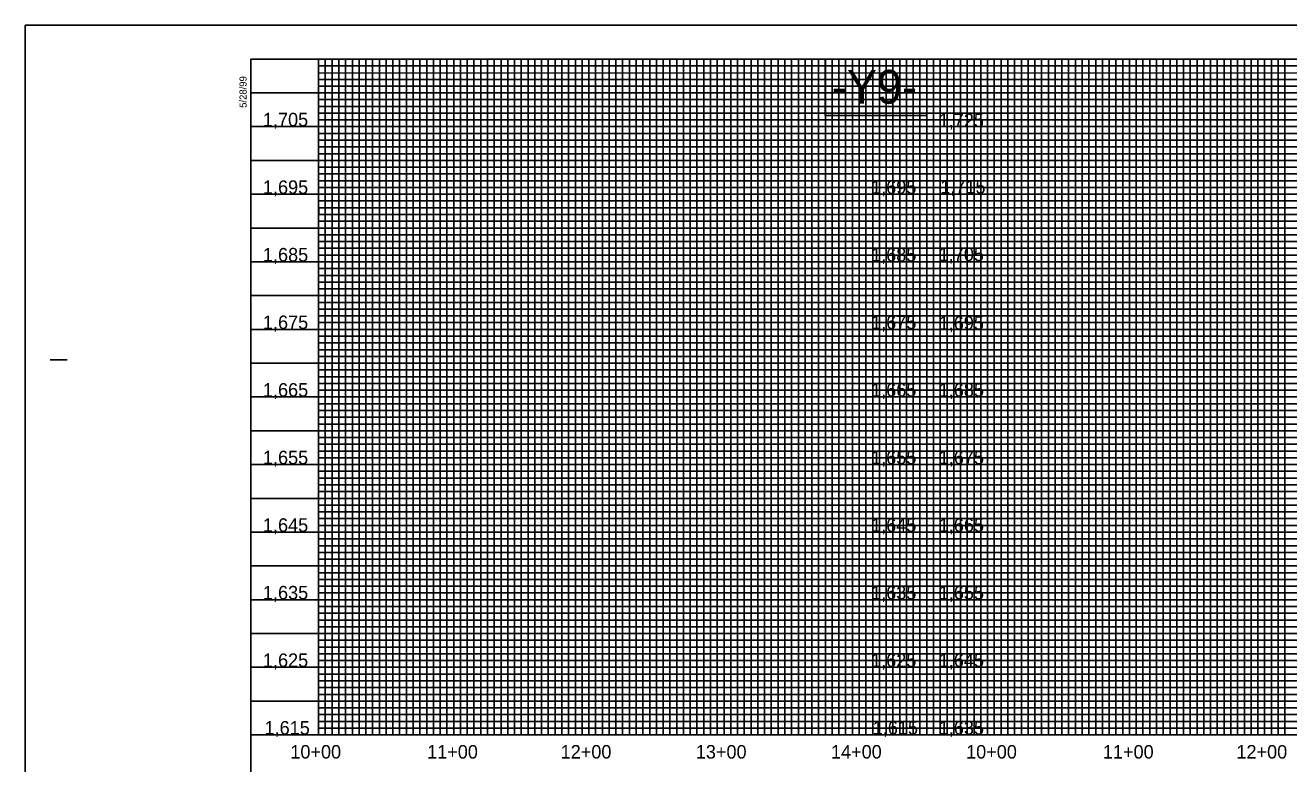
# Model space of a CAD drawing. Extents: x 502400 to 509344, y 448070 to 484209.
# Drawn here: x 505602 to 506537, y 483662 to 484209 of the extents above; entities that cross this region are included whole.
import ezdxf

# ---------------------------------------------------------------- set-up
doc = ezdxf.new("R2010")
doc.units = 0
for name, color, linetype in [('Exist Vertical Profile Vertical Axis Label', 7, 'Continuous'), ('Old_Level_1', 7, 'Continuous'), ('Prop Grid Mask', 7, 'Continuous'), ('Sheet Layout Profile Border Port 1', 7, 'Continuous'), ('Sheet Layout Profile Border Port 2', 7, 'Continuous'), ('Sheet Plot Border Outside CELL', 7, 'Continuous'), ('Sheet Profile CELL', 7, 'Continuous'), ('Sheet Profile Grid Major CELL', 7, 'Continuous'), ('Sheet Profile Grid Middle CELL', 7, 'Continuous'), ('Sheet Profile Grid Minor CELL', 7, 'Continuous')]:
    doc.layers.add(name, color=color, linetype=linetype)

msp = doc.modelspace()

# ---------------------------------------------------------------- linework, layer by layer
at = {"layer": 'Prop Grid Mask'}
msp.add_lwpolyline([(506269.08, 484183.71), (506193.91, 484183.71), (506193.91, 484142), (506269.08, 484142)], close=True, dxfattribs=at)
at = {"layer": 'Sheet Layout Profile Border Port 1'}
msp.add_lwpolyline([(505819.08, 484183.71), (506219.08, 484183.71), (506219.08, 483683.71), (505819.08, 483683.71)], close=True, dxfattribs=at)
at = {"layer": 'Sheet Layout Profile Border Port 2'}
msp.add_lwpolyline([(506269.08, 484183.71), (506769.05, 484183.71), (506769.05, 483683.71), (506269.08, 483683.71)], close=True, dxfattribs=at)
at = {"layer": 'Sheet Plot Border Outside CELL'}
msp.add_lwpolyline([(505602.08, 483108.71), (507286.08, 483108.71), (507286.08, 484208.71), (505602.08, 484208.71)], close=True, dxfattribs=at)
at = {"layer": 'Sheet Profile CELL'}
for p, q in [((506269.08, 483683.71), (506269.08, 484183.71)), ((505620.58, 483961.21), (505633.08, 483961.21)), ((505769.08, 483683.71), (507269.08, 483683.71))]:
    msp.add_line(p, q, dxfattribs=at)
msp.add_lwpolyline([(507269.08, 484183.71), (505769.08, 484183.71), (505769.08, 483133.71), (507269.08, 483133.71)], close=True, dxfattribs=at)
at = {"layer": 'Sheet Profile Grid Major CELL'}
for points in [[(505819.08, 484183.71), (505819.08, 483683.71), (505869.08, 483683.71), (505869.08, 484183.71), (505919.08, 484183.71), (505919.08, 483683.71), (505969.08, 483683.71), (505969.08, 484183.71), (506019.08, 484183.71), (506019.08, 483683.71), (506069.08, 483683.71), (506069.08, 484183.71), (506119.08, 484183.71), (506119.08, 483683.71), (506169.08, 483683.71), (506169.08, 484183.71), (506219.08, 484183.71), (506219.08, 483683.71), (506269.08, 483683.71), (506269.08, 484183.71), (506319.08, 484183.71), (506319.08, 483683.71), (506369.08, 483683.71), (506369.08, 484183.71), (506419.08, 484183.71), (506419.08, 483683.71), (506469.08, 483683.71), (506469.08, 484183.71), (506519.08, 484183.71), (506519.08, 483683.71), (506569.08, 483683.71)], [(505769.08, 484133.71), (507069.08, 484133.71)], [(507069.08, 484083.71), (505769.08, 484083.71), (505769.08, 484033.71), (507069.08, 484033.71)], [(507269.08, 483983.71), (505769.08, 483983.71), (505769.08, 483933.71), (507269.08, 483933.71)], [(507269.08, 483883.71), (505769.08, 483883.71), (505769.08, 483833.71), (507269.08, 483833.71)], [(507269.08, 483783.71), (505769.08, 483783.71), (505769.08, 483783.71), (505769.08, 483733.71), (507269.08, 483733.71)]]:
    msp.add_lwpolyline(points, dxfattribs=at)
at = {"layer": 'Sheet Profile Grid Middle CELL'}
msp.add_line((505769.08, 484158.71), (507069.03, 484158.71), dxfattribs=at)
msp.add_line((505769.08, 484158.71), (507069.03, 484158.71), dxfattribs=at)
for points in [[(505844.08, 484183.71), (505844.08, 483683.71), (505894.08, 483683.71), (505894.08, 484183.71), (505944.08, 484183.71), (505944.08, 483683.71), (505994.08, 483683.71), (505994.08, 484183.71), (506044.08, 484183.71), (506044.08, 483683.71), (506094.08, 483683.71), (506094.08, 484183.71), (506144.08, 484183.71), (506144.08, 483683.71), (506194.08, 483683.71), (506194.08, 484183.71), (506244.08, 484183.71), (506244.08, 483683.71), (506294.08, 483683.71), (506294.08, 484183.71), (506344.08, 484183.71), (506344.08, 483683.71), (506394.08, 483683.71), (506394.08, 483683.71), (506394.08, 484183.71), (506444.08, 484183.71), (506444.08, 483683.71), (506494.08, 483683.71), (506494.08, 484183.71), (506544.08, 484183.71)], [(507069.08, 484108.71), (505769.08, 484108.71), (505769.08, 484058.71), (507069.08, 484058.71)], [(507269.08, 484008.71), (505769.08, 484008.71), (505769.08, 483958.71), (507094.08, 483958.71)], [(507269.08, 483908.71), (505769.08, 483908.71), (505769.08, 483858.71), (507269.08, 483858.71)], [(507269.08, 483808.71), (505769.08, 483808.71), (505769.08, 483758.71), (507269.08, 483758.71)], [(507269.08, 483708.71), (505769.08, 483708.71)]]:
    msp.add_lwpolyline(points, dxfattribs=at)
at = {"layer": 'Sheet Profile Grid Minor CELL'}
for p, q in [((505819.08, 484178.71), (507069.08, 484178.71)), ((505819.08, 484173.71), (505819.08, 484173.71)), ((507069.08, 484173.71), (505819.08, 484173.36)), ((505819.08, 484168.71), (507069.08, 484168.71)), ((507069.03, 484048.71), (505819.08, 484048.71)), ((507069.08, 484043.71), (505819.08, 484043.71)), ((507069.08, 484038.71), (505819.08, 484038.71)), ((505819.08, 484028.71), (507069.08, 484028.71)), ((507069.08, 484023.71), (505819.08, 484023.71)), ((505819.08, 484018.71), (507219.08, 484018.71)), ((507219.08, 483998.71), (505819.08, 483998.71)), ((505819.08, 483993.71), (507219.08, 483993.71)), ((507219.08, 483973.71), (505819.08, 483973.71)), ((505819.08, 483968.71), (507219.08, 483968.71)), ((507219.08, 483948.71), (505819.08, 483948.71)), ((505819.08, 483943.71), (507219.08, 483943.71)), ((507219.08, 483938.71), (505819.08, 483938.71)), ((505819.08, 483928.71), (507219.08, 483928.71)), ((507219.08, 483923.71), (505819.08, 483923.71)), ((505819.08, 483918.71), (507219.08, 483918.71)), ((507219.08, 483913.71), (505819.08, 483913.71)), ((505819.08, 483903.71), (507219.08, 483903.71)), ((507219.08, 483898.71), (505819.08, 483898.71)), ((505819.08, 483893.71), (507219.08, 483893.71)), ((507219.08, 483888.71), (505819.08, 483888.71)), ((505819.08, 483878.71), (507219.08, 483878.71)), ((507219.08, 483873.71), (505819.08, 483873.71)), ((505819.08, 483868.71), (507219.08, 483868.71)), ((507219.08, 483863.71), (505819.08, 483863.71)), ((505819.08, 483853.71), (507219.08, 483853.71)), ((507219.08, 483848.71), (505819.08, 483848.71)), ((505819.08, 483843.71), (507219.08, 483843.71)), ((507219.08, 483838.71), (505819.08, 483838.71)), ((505819.08, 483828.71), (507219.08, 483828.71)), ((507219.08, 483823.71), (505819.08, 483823.71)), ((505819.08, 483818.71), (507219.08, 483818.71)), ((507219.08, 483813.71), (505819.08, 483813.71)), ((505819.08, 483803.71), (507219.08, 483803.71)), ((507219.08, 483798.71), (505819.08, 483798.71)), ((507219.08, 483793.71), (505819.08, 483793.71)), ((507219.08, 483788.71), (505819.08, 483788.71)), ((505819.08, 483778.71), (507219.08, 483778.71)), ((507219.08, 483773.71), (505819.08, 483773.71)), ((505819.08, 483768.71), (507219.08, 483768.71)), ((507219.08, 483763.71), (505819.08, 483763.71)), ((505819.08, 483753.71), (507219.08, 483753.71)), ((507219.08, 483748.71), (505819.08, 483748.71)), ((505819.08, 483743.71), (507219.08, 483743.71)), ((507219.08, 483738.71), (505819.08, 483738.71)), ((505819.08, 483728.71), (507219.08, 483728.71)), ((507219.08, 483723.71), (505819.08, 483723.71)), ((505819.08, 483718.71), (507219.08, 483718.71)), ((507219.08, 483713.71), (505819.08, 483713.71)), ((505819.08, 483703.71), (507219.08, 483703.71)), ((507219.08, 483698.71), (505819.08, 483698.71)), ((505819.08, 483693.71), (507219.08, 483693.71))]:
    msp.add_line(p, q, dxfattribs=at)
for points in [[(505824.08, 484183.71), (505824.08, 483683.71), (505829.08, 483683.71), (505829.08, 484183.71), (505834.08, 484183.71), (505834.08, 483683.71), (505839.08, 483683.71), (505839.08, 484183.71), (505849.08, 484183.71), (505849.08, 483683.71), (505854.08, 483683.71), (505854.08, 484183.71), (505859.08, 484183.71), (505859.08, 483683.71), (505864.08, 483683.71), (505874.08, 483683.71), (505879.08, 483683.71), (505879.08, 484183.71), (505884.08, 484183.71), (505884.08, 483683.71), (505889.08, 483683.71), (505889.08, 484183.71), (505899.08, 484183.71), (505899.08, 483683.71), (505904.08, 483683.71), (505904.08, 484183.71), (505909.08, 484183.71), (505909.08, 483683.71), (505914.08, 483683.71), (505914.08, 484183.71), (505924.08, 484183.71), (505924.08, 483683.71), (505929.08, 483683.71), (505929.08, 484183.71), (505934.08, 484183.71), (505934.08, 483683.71), (505939.08, 483683.71), (505939.08, 484183.71), (505949.08, 484183.71), (505949.08, 483683.71), (505954.08, 483683.71), (505954.08, 484183.71), (505959.08, 484183.71), (505959.08, 483683.71), (505964.08, 483683.71), (505964.08, 484183.71), (505974.08, 484183.71), (505974.08, 483683.71), (505979.08, 483683.71), (505979.08, 484183.71), (505984.08, 484183.71), (505984.08, 483683.71), (505989.08, 483683.71), (505989.08, 484183.71), (505999.08, 484183.71), (505999.08, 483683.71), (506004.08, 483683.71), (506004.08, 484183.71), (506009.08, 484183.71), (506009.08, 483683.71), (506014.08, 483683.71), (506014.08, 484183.71), (506024.08, 484183.71), (506024.08, 483683.71), (506029.08, 483683.71), (506029.08, 484183.71), (506034.08, 484183.71), (506034.08, 483683.71)], [(505864.08, 483683.71), (505864.08, 484183.71), (505874.08, 484183.71), (505874.08, 483683.71)], [(506034.08, 483683.71), (506039.08, 483683.71), (506039.08, 484183.71), (506049.08, 484183.71), (506049.08, 483683.71), (506054.08, 483683.71), (506054.08, 484183.71), (506059.08, 484183.71), (506059.08, 483683.71), (506064.08, 483683.71), (506064.08, 484183.71), (506074.08, 484183.71), (506074.08, 483683.71), (506079.08, 483683.71), (506079.08, 484183.71), (506084.08, 484183.71), (506084.08, 483683.71), (506089.08, 483683.71), (506089.08, 484183.71), (506099.08, 484183.71), (506099.08, 483683.71), (506104.08, 483683.71), (506104.08, 484183.71), (506109.08, 484183.71), (506109.08, 483683.71), (506114.08, 483683.71), (506114.08, 484183.71), (506124.08, 484183.71), (506124.08, 483683.71), (506129.08, 483683.71), (506129.08, 484183.71), (506134.08, 484183.71), (506134.08, 483683.71), (506139.08, 483683.71), (506139.08, 484183.71), (506149.08, 484183.71), (506149.08, 483683.71), (506154.08, 483683.71), (506154.08, 484183.71), (506159.08, 484183.71), (506159.08, 483683.71), (506164.08, 483683.71), (506164.08, 484183.71), (506174.08, 484183.71), (506174.08, 483683.71), (506179.08, 483683.71), (506179.08, 484183.71), (506184.08, 484183.71), (506184.08, 483683.71), (506189.08, 483683.71), (506189.08, 484183.71), (506199.08, 484183.71), (506199.08, 483683.71), (506204.08, 483683.71), (506204.08, 484183.71), (506209.08, 484183.71), (506209.08, 483683.71), (506214.08, 483683.71), (506214.08, 484183.71), (506224.08, 484183.71), (506224.08, 483683.71), (506229.08, 483683.71), (506229.08, 484183.71), (506234.08, 484183.71), (506234.08, 483683.71), (506239.08, 483683.71), (506239.08, 484183.71), (506249.08, 484183.71), (506249.08, 483683.71), (506254.08, 483683.71), (506254.08, 484183.71), (506259.08, 484183.71), (506259.08, 483683.71), (506264.08, 483683.71), (506264.08, 484183.71), (506274.08, 484183.71), (506274.08, 483683.71), (506279.08, 483683.71), (506279.08, 484183.71), (506284.08, 484183.71), (506284.08, 483683.71), (506289.08, 483683.71), (506289.08, 484183.71), (506299.08, 484183.71), (506299.08, 483683.71), (506304.08, 483683.71), (506304.08, 484183.71), (506309.08, 484183.71), (506309.08, 483683.71), (506314.08, 483683.71), (506314.08, 484183.71), (506324.08, 484183.71), (506324.08, 483683.71), (506329.08, 483683.71), (506329.08, 484183.71), (506334.08, 484183.71), (506334.08, 483683.71), (506339.08, 483683.71), (506339.08, 484183.71), (506349.08, 484183.71)], [(506349.08, 484183.71), (506349.08, 483683.71), (506354.08, 483683.71), (506354.08, 484183.71), (506359.08, 484183.71), (506359.08, 483683.71), (506364.08, 483683.71), (506364.08, 484183.71), (506374.08, 484183.71), (506374.08, 483683.71), (506379.08, 483683.71), (506379.08, 484183.71), (506384.08, 484183.71), (506384.08, 483683.71), (506389.08, 483683.71), (506389.08, 484183.71), (506399.08, 484183.71), (506399.08, 483683.71), (506404.08, 483683.71), (506404.08, 484183.71), (506409.08, 484183.71), (506409.08, 483683.71), (506414.08, 483683.71), (506414.08, 484183.71), (506424.08, 484183.71), (506424.08, 483683.71), (506429.08, 483683.71), (506429.08, 484183.71), (506434.08, 484183.71), (506434.08, 483683.71), (506439.08, 483683.71), (506439.08, 484183.71), (506449.08, 484183.71), (506449.08, 483683.71), (506454.08, 483683.71), (506454.08, 484183.71), (506459.08, 484183.71), (506459.08, 483683.71), (506464.08, 483683.71), (506464.08, 484183.71), (506474.08, 484183.71), (506474.08, 483683.71), (506474.08, 483683.71), (506479.08, 483683.71), (506479.08, 484183.71), (506484.08, 484183.71), (506484.08, 483683.71), (506489.08, 483683.71), (506489.08, 484183.71), (506499.08, 484183.71), (506499.08, 483683.71), (506504.08, 483683.71), (506504.08, 484183.71), (506509.08, 484183.71), (506509.08, 483683.71), (506514.08, 483683.71), (506514.08, 484183.71), (506524.08, 484183.71), (506524.08, 483683.71), (506529.08, 483683.71), (506529.08, 484183.71), (506534.08, 484183.71), (506534.08, 483683.71), (506539.08, 483683.71)], [(507069.08, 484163.71), (505819.08, 484163.71), (505819.08, 484153.71), (507069.08, 484153.71)], [(507069.03, 484148.71), (505819.08, 484148.71), (505819.08, 484143.71), (507069.08, 484143.71)], [(507069.08, 484138.71), (505819.08, 484138.71), (505819.08, 484128.71), (507069.08, 484128.71)], [(507069.08, 484123.71), (505819.08, 484123.71), (505819.08, 484118.71), (507069.08, 484118.71)], [(507069.08, 484113.71), (505819.08, 484113.71), (505819.08, 484103.71), (507069.08, 484103.71)], [(507069.08, 484098.71), (505819.08, 484098.71), (505819.08, 484093.71), (507069.08, 484093.71)], [(507069.08, 484088.71), (505819.08, 484088.71), (505819.08, 484078.71), (507069.08, 484078.71)], [(507069.08, 484073.61), (505819.18, 484073.61), (505819.18, 484068.71), (507069.08, 484068.71)], [(507069.08, 484063.71), (505819.08, 484063.71), (505819.08, 484053.71), (507069.08, 484053.71)], [(507219.08, 484013.71), (505819.08, 484013.71), (505819.08, 484003.71), (507219.08, 484003.71)], [(507219.08, 483988.71), (505819.08, 483988.71), (505819.08, 483978.71), (507219.08, 483978.71)], [(507219.08, 483963.71), (505819.08, 483963.71), (505819.08, 483953.71), (507219.08, 483953.71)], [(507219.08, 483688.71), (505819.08, 483688.71)]]:
    msp.add_lwpolyline(points, dxfattribs=at)

# ---------------------------------------------------------------- texts
at = {"layer": 'Exist Vertical Profile Vertical Axis Label'}
for s, p in [('1,705', (505777.93, 484133.96)), ('1,725', (506277.93, 484133.4)), ('1,695', (505777.93, 484083.96)), ('1,695', (506227.93, 484083.96)), ('1,715', (506279.13, 484084.19)), ('1,685', (505777.93, 484033.96)), ('1,685', (506227.93, 484033.96)), ('1,705', (506277.93, 484034.26)), ('1,675', (505777.93, 483983.96)), ('1,675', (506227.93, 483983.96)), ('1,695', (506277.93, 483983.48)), ('1,665', (505777.93, 483933.96)), ('1,665', (506227.93, 483933.96)), ('1,685', (506277.97, 483933.96)), ('1,655', (505777.93, 483883.96)), ('1,655', (506227.93, 483883.96)), ('1,675', (506277.97, 483883.96)), ('1,645', (505777.93, 483833.96)), ('1,645', (506227.93, 483833.96)), ('1,665', (506277.97, 483833.96)), ('1,635', (505777.93, 483783.96)), ('1,635', (506227.93, 483783.96)), ('1,655', (506277.97, 483783.96)), ('1,625', (505777.93, 483733.96)), ('1,625', (506227.93, 483733.96)), ('1,645', (506277.97, 483733.96)), ('1,615', (505779.13, 483683.96)), ('1,615', (506229.13, 483683.96)), ('1,635', (506277.97, 483683.96)), ('10+00', (505798.21, 483666.21)), ('11+00', (505899.41, 483666.21)), ('12+00', (505998.21, 483666.21)), ('13+00', (506098.21, 483666.21)), ('14+00', (506198.21, 483666.21)), ('10+00', (506298.21, 483666.21)), ('11+00', (506399.41, 483666.21)), ('12+00', (506498.21, 483666.21))]:
    msp.add_text(s, height=10, dxfattribs=at).set_placement(p)
at = {"layer": 'Old_Level_1'}
msp.add_text('-Y9-', height=25, dxfattribs=at).set_placement((506198.82, 484150.68))
at = {"layer": 'Sheet Profile CELL'}
msp.add_text('5/28/99', height=5.25, rotation=90, dxfattribs=at).set_placement((505765.84, 484147.62))

doc.saveas('drawing.dxf')
